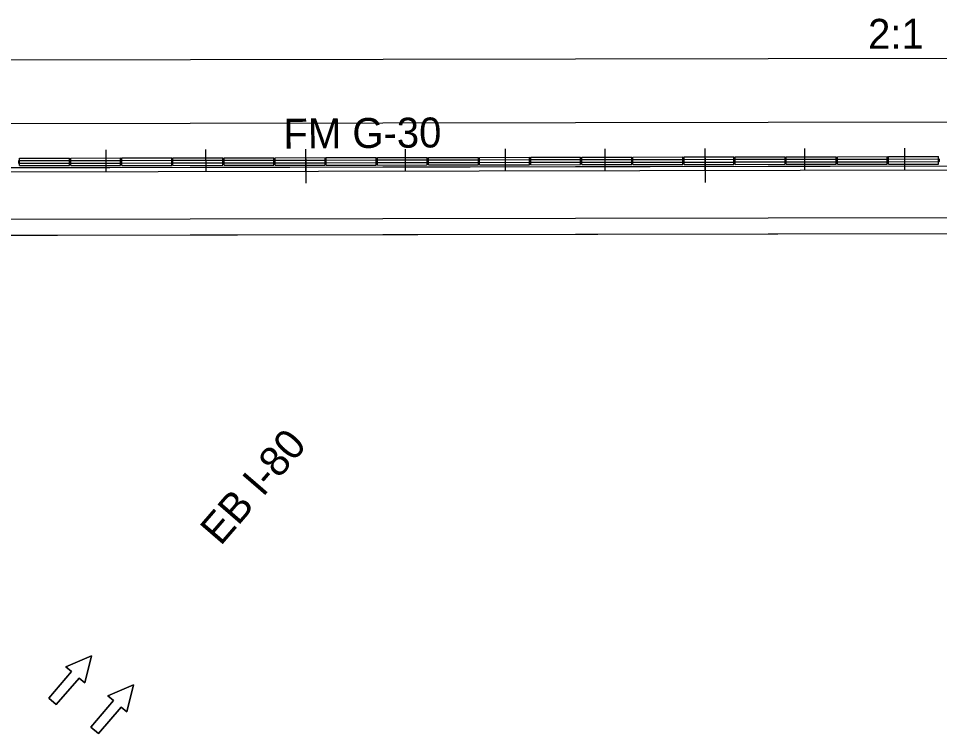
# Model space of a CAD drawing. Extents: x 16513048 to 16518780, y 7009856 to 7010869.
# Drawn here: x 16515768.8 to 16515999.5, y 7010216.8 to 7010396 of the extents above; entities that cross this region are included whole.
import ezdxf

# ---------------------------------------------------------------- set-up
doc = ezdxf.new("R2010")
doc.units = 0
for name, color, linetype in [('Dimensions', 7, 'Continuous'), ('dsnCellElements', 7, 'Continuous'), ('dsnNonPlotable', 7, 'Continuous'), ('EdgePaved', 7, 'Continuous'), ('Level 2', 7, 'Continuous'), ('Level 5', 7, 'Continuous'), ('Shape', 7, 'Continuous'), ('SheetBorder', 7, 'Continuous'), ('tdCoTitleBlock', 7, 'Continuous')]:
    doc.layers.add(name, color=color, linetype=linetype)

msp = doc.modelspace()

# ---------------------------------------------------------------- linework, layer by layer
at = {"layer": 'dsnCellElements'}
for p, q in [((16515922.71, 7010361.3), (16515935.21, 7010361.32)), ((16515935.22, 7010359.44), (16515935.21, 7010361.32)), ((16515935.52, 7010361.32), (16515948.02, 7010361.34)), ((16515935.52, 7010359.44), (16515935.52, 7010361.32)), ((16515948.02, 7010359.46), (16515948.02, 7010361.34)), ((16515948.32, 7010361.34), (16515960.82, 7010361.36)), ((16515948.32, 7010359.47), (16515948.32, 7010361.34)), ((16515960.82, 7010359.49), (16515960.82, 7010361.36)), ((16515961.12, 7010361.36), (16515973.62, 7010361.38)), ((16515961.12, 7010359.49), (16515961.12, 7010361.36)), ((16515973.62, 7010359.51), (16515973.62, 7010361.38)), ((16515973.92, 7010361.38), (16515986.42, 7010361.41)), ((16515973.93, 7010359.51), (16515973.92, 7010361.38)), ((16515986.43, 7010359.53), (16515986.42, 7010361.41)), ((16515986.73, 7010361.41), (16515999.23, 7010361.43)), ((16515986.73, 7010359.53), (16515986.73, 7010361.41)), ((16515999.23, 7010359.55), (16515999.23, 7010361.43)), ((16515769.09, 7010361.03), (16515781.59, 7010361.05)), ((16515769.09, 7010359.15), (16515769.09, 7010361.03)), ((16515769.09, 7010360.43), (16515781.59, 7010360.45)), ((16515769.09, 7010359.75), (16515781.59, 7010359.77)), ((16515769.09, 7010359.15), (16515781.59, 7010359.17)), ((16515781.59, 7010359.17), (16515781.59, 7010361.05)), ((16515781.89, 7010361.05), (16515794.39, 7010361.07)), ((16515781.89, 7010359.17), (16515781.89, 7010361.05)), ((16515781.89, 7010360.45), (16515794.39, 7010360.47)), ((16515781.89, 7010359.77), (16515794.39, 7010359.8)), ((16515781.89, 7010359.17), (16515794.39, 7010359.2)), ((16515794.39, 7010359.2), (16515794.39, 7010361.07)), ((16515794.69, 7010361.07), (16515807.19, 7010361.09)), ((16515794.7, 7010359.2), (16515794.69, 7010361.07)), ((16515794.69, 7010360.47), (16515807.19, 7010360.49)), ((16515794.7, 7010359.8), (16515807.2, 7010359.82)), ((16515794.7, 7010359.2), (16515807.2, 7010359.22)), ((16515807.2, 7010359.22), (16515807.19, 7010361.09)), ((16515807.5, 7010361.09), (16515820, 7010361.12)), ((16515807.5, 7010359.22), (16515807.5, 7010361.09)), ((16515807.5, 7010360.49), (16515820, 7010360.52)), ((16515807.5, 7010359.82), (16515820, 7010359.84)), ((16515807.5, 7010359.22), (16515820, 7010359.24)), ((16515820, 7010359.24), (16515820, 7010361.12)), ((16515820.3, 7010361.12), (16515832.8, 7010361.14)), ((16515820.3, 7010359.24), (16515820.3, 7010361.12)), ((16515820.3, 7010360.52), (16515832.8, 7010360.54)), ((16515820.3, 7010359.84), (16515832.8, 7010359.86)), ((16515820.3, 7010359.24), (16515832.8, 7010359.26)), ((16515832.8, 7010359.26), (16515832.8, 7010361.14)), ((16515833.1, 7010361.14), (16515845.6, 7010361.16)), ((16515833.1, 7010359.26), (16515833.1, 7010361.14)), ((16515833.1, 7010360.54), (16515845.6, 7010360.56)), ((16515833.1, 7010359.86), (16515845.6, 7010359.89)), ((16515833.1, 7010359.26), (16515845.6, 7010359.29)), ((16515845.6, 7010359.29), (16515845.6, 7010361.16)), ((16515845.9, 7010361.16), (16515858.4, 7010361.18)), ((16515845.91, 7010359.29), (16515845.9, 7010361.16)), ((16515845.9, 7010360.56), (16515858.4, 7010360.58)), ((16515845.9, 7010359.89), (16515858.4, 7010359.91)), ((16515845.91, 7010359.29), (16515858.41, 7010359.31)), ((16515858.41, 7010359.31), (16515858.4, 7010361.18)), ((16515858.7, 7010361.18), (16515871.2, 7010361.21)), ((16515858.71, 7010359.31), (16515858.7, 7010361.18)), ((16515858.71, 7010360.58), (16515871.21, 7010360.61)), ((16515858.71, 7010359.91), (16515871.21, 7010359.93)), ((16515858.71, 7010359.31), (16515871.21, 7010359.33)), ((16515871.21, 7010359.33), (16515871.2, 7010361.21)), ((16515871.51, 7010361.21), (16515884.01, 7010361.23)), ((16515871.51, 7010359.33), (16515871.51, 7010361.21)), ((16515871.51, 7010360.61), (16515884.01, 7010360.63)), ((16515871.51, 7010359.93), (16515884.01, 7010359.95)), ((16515871.51, 7010359.33), (16515884.01, 7010359.35)), ((16515884.01, 7010359.35), (16515884.01, 7010361.23)), ((16515884.31, 7010361.23), (16515896.81, 7010361.25)), ((16515884.31, 7010359.35), (16515884.31, 7010361.23)), ((16515884.31, 7010360.63), (16515896.81, 7010360.65)), ((16515884.31, 7010359.95), (16515896.81, 7010359.98)), ((16515884.31, 7010359.35), (16515896.81, 7010359.38)), ((16515896.81, 7010359.38), (16515896.81, 7010361.25)), ((16515897.11, 7010361.25), (16515909.61, 7010361.27)), ((16515897.11, 7010359.38), (16515897.11, 7010361.25)), ((16515897.11, 7010360.65), (16515909.61, 7010360.67)), ((16515897.11, 7010359.98), (16515909.61, 7010360)), ((16515897.11, 7010359.38), (16515909.61, 7010359.4)), ((16515909.61, 7010359.4), (16515909.61, 7010361.27)), ((16515909.91, 7010361.27), (16515922.41, 7010361.29)), ((16515909.92, 7010359.4), (16515909.91, 7010361.27)), ((16515909.91, 7010360.67), (16515922.41, 7010360.69)), ((16515909.91, 7010360), (16515922.41, 7010360.02)), ((16515909.92, 7010359.4), (16515922.42, 7010359.42)), ((16515922.42, 7010359.42), (16515922.41, 7010361.29)), ((16515922.72, 7010359.42), (16515922.71, 7010361.3)), ((16515922.72, 7010360.7), (16515935.22, 7010360.72)), ((16515922.72, 7010360.02), (16515935.22, 7010360.04)), ((16515922.72, 7010359.42), (16515935.22, 7010359.44)), ((16515935.52, 7010360.72), (16515948.02, 7010360.74)), ((16515935.52, 7010360.04), (16515948.02, 7010360.06)), ((16515935.52, 7010359.44), (16515948.02, 7010359.46)), ((16515948.32, 7010360.74), (16515960.82, 7010360.76)), ((16515948.32, 7010360.07), (16515960.82, 7010360.09)), ((16515948.32, 7010359.47), (16515960.82, 7010359.49)), ((16515961.12, 7010360.76), (16515973.62, 7010360.78)), ((16515961.12, 7010360.09), (16515973.62, 7010360.11)), ((16515961.12, 7010359.49), (16515973.62, 7010359.51)), ((16515973.92, 7010360.78), (16515986.42, 7010360.81)), ((16515973.93, 7010360.11), (16515986.43, 7010360.13)), ((16515973.93, 7010359.51), (16515986.43, 7010359.53)), ((16515986.73, 7010360.81), (16515999.23, 7010360.83)), ((16515986.73, 7010360.13), (16515999.23, 7010360.15)), ((16515986.73, 7010359.53), (16515999.23, 7010359.55))]:
    msp.add_line(p, q, dxfattribs=at)
at = {"layer": 'dsnNonPlotable'}
msp.add_line((16513050.27, 7010352.91), (16516699.62, 7010359.27), dxfattribs=at)
for points in [[(16513050.22, 7010380.91), (16516699.59, 7010387.27), (16518770.65, 7010388.94)], [(16518770.66, 7010372.94), (16516699.61, 7010371.27), (16513050.25, 7010364.91)], [(16518770.68, 7010348.94), (16516699.64, 7010347.27), (16513050.29, 7010340.91)], [(16518770.69, 7010344.94), (16516699.64, 7010343.27), (16513050.3, 7010336.91)]]:
    msp.add_lwpolyline(points, dxfattribs=at)
at = {"layer": 'EdgePaved'}
for centre in [(16515768.94, 7010360.09), (16515768.94, 7010360.09), (16515781.74, 7010360.11), (16515781.74, 7010360.11), (16515794.54, 7010360.13), (16515794.54, 7010360.13), (16515807.35, 7010360.16), (16515807.35, 7010360.16), (16515820.15, 7010360.18), (16515820.15, 7010360.18), (16515832.95, 7010360.2), (16515832.95, 7010360.2), (16515845.75, 7010360.22), (16515845.75, 7010360.22), (16515858.55, 7010360.25), (16515858.55, 7010360.25), (16515871.36, 7010360.27), (16515871.36, 7010360.27), (16515884.16, 7010360.29), (16515884.16, 7010360.29), (16515896.96, 7010360.31), (16515896.96, 7010360.31), (16515909.76, 7010360.34), (16515909.76, 7010360.34), (16515922.57, 7010360.36), (16515922.57, 7010360.36), (16515935.37, 7010360.38), (16515935.37, 7010360.38), (16515948.17, 7010360.4), (16515948.17, 7010360.4), (16515960.97, 7010360.42), (16515960.97, 7010360.42), (16515973.77, 7010360.45), (16515973.77, 7010360.45), (16515986.58, 7010360.47), (16515986.58, 7010360.47), (16515999.38, 7010360.49), (16515999.38, 7010360.49)]:
    msp.add_circle(centre, 0.0521, dxfattribs=at)
for centre, start, end in [((16515768.79, 7010360.09), 270.0999, 90.0999), ((16515769.09, 7010360.09), 90.0999, 270.0999), ((16515781.59, 7010360.11), 270.0999, 90.0999), ((16515781.89, 7010360.11), 90.0999, 270.0999), ((16515794.39, 7010360.13), 270.0999, 90.0999), ((16515794.69, 7010360.13), 90.0999, 270.0999), ((16515807.2, 7010360.16), 270.0999, 90.0999), ((16515807.5, 7010360.16), 90.0999, 270.0999), ((16515820, 7010360.18), 270.0999, 90.0999), ((16515820.3, 7010360.18), 90.0999, 270.0999), ((16515832.8, 7010360.2), 270.0999, 90.0999), ((16515833.1, 7010360.2), 90.0999, 270.0999), ((16515845.6, 7010360.22), 270.0999, 90.0999), ((16515845.9, 7010360.22), 90.0999, 270.0999), ((16515858.4, 7010360.25), 270.0999, 90.0999), ((16515858.71, 7010360.25), 90.0999, 270.0999), ((16515871.21, 7010360.27), 270.0999, 90.0999), ((16515871.51, 7010360.27), 90.0999, 270.0999), ((16515884.01, 7010360.29), 270.0999, 90.0999), ((16515884.31, 7010360.29), 90.0999, 270.0999), ((16515896.81, 7010360.31), 270.0999, 90.0999), ((16515897.11, 7010360.31), 90.0999, 270.0999), ((16515909.61, 7010360.34), 270.0999, 90.0999), ((16515909.91, 7010360.34), 90.0999, 270.0999), ((16515922.41, 7010360.36), 270.0999, 90.0999), ((16515922.72, 7010360.36), 90.0999, 270.0999), ((16515935.22, 7010360.38), 270.0999, 90.0999), ((16515935.52, 7010360.38), 90.0999, 270.0999), ((16515948.02, 7010360.4), 270.0999, 90.0999), ((16515948.32, 7010360.4), 90.0999, 270.0999), ((16515960.82, 7010360.42), 270.0999, 90.0999), ((16515961.12, 7010360.42), 90.0999, 270.0999), ((16515973.62, 7010360.45), 270.0999, 90.0999), ((16515973.92, 7010360.45), 90.0999, 270.0999), ((16515986.42, 7010360.47), 270.0999, 90.0999), ((16515986.73, 7010360.47), 90.0999, 270.0999), ((16515999.23, 7010360.49), 270.0999, 90.0999), ((16515999.53, 7010360.49), 90.0999, 270.0999)]:
    msp.add_arc(centre, 0.281, start, end, dxfattribs=at)
at = {"layer": 'Level 2'}
for points in [[(16515778.29, 7010224.09), (16515776.39, 7010225.72), (16515782.08, 7010232.36), (16515780.66, 7010233.58), (16515787.1, 7010236.29), (16515785.4, 7010229.51), (16515783.98, 7010230.73)], [(16515788.84, 7010216.83), (16515786.94, 7010218.46), (16515792.64, 7010225.1), (16515791.21, 7010226.32), (16515797.65, 7010229.04), (16515795.96, 7010222.26), (16515794.54, 7010223.48)]]:
    msp.add_lwpolyline(points, close=True, dxfattribs=at)
at = {"layer": 'Level 5'}
for points in [[(16515783.98, 7010230.73), (16515785.4, 7010229.51), (16515787.1, 7010236.29), (16515780.66, 7010233.58), (16515782.08, 7010232.36), (16515776.39, 7010225.72), (16515778.29, 7010224.09), (16515783.98, 7010230.73)], [(16515794.54, 7010223.48), (16515795.96, 7010222.26), (16515797.65, 7010229.04), (16515791.21, 7010226.32), (16515792.64, 7010225.1), (16515786.94, 7010218.46), (16515788.84, 7010216.83), (16515794.54, 7010223.48)]]:
    msp.add_lwpolyline(points, dxfattribs=at)
at = {"layer": 'Shape'}
msp.add_line((16516114.45, 7010359.25), (16515602.67, 7010358.36), dxfattribs=at)
msp.add_lwpolyline([(16516017.16, 7010359.09), (16516004.05, 7010342.06), (16515688.36, 7010341.51), (16515701.47, 7010358.53), (16516017.16, 7010359.09)], close=True, dxfattribs=at)
at = {"layer": 'SheetBorder'}
for p, q in [((16515790.79, 7010357.69), (16515790.78, 7010363.15)), ((16515815.79, 7010357.73), (16515815.78, 7010363.19)), ((16515865.79, 7010357.82), (16515865.78, 7010363.28)), ((16515890.79, 7010357.86), (16515890.78, 7010363.32)), ((16515915.79, 7010357.91), (16515915.78, 7010363.37)), ((16515965.79, 7010358), (16515965.78, 7010363.46)), ((16515990.79, 7010358.04), (16515990.78, 7010363.5)), ((16515840.78, 7010360.84), (16515840.8, 7010354.72)), ((16515940.78, 7010361.01), (16515940.8, 7010354.89))]:
    msp.add_line(p, q, dxfattribs=at)
at = {"layer": 'tdCoTitleBlock'}
for p, q in [((16515840.79, 7010357.78), (16515840.78, 7010363.24)), ((16515940.79, 7010357.95), (16515940.78, 7010363.41))]:
    msp.add_line(p, q, dxfattribs=at)

# ---------------------------------------------------------------- texts
at = {"layer": 'Dimensions'}
for s, rotation, p in [('FM G-30', 0.4439, (16515835.2, 7010363.42)), ('EB I-80', 49.1804, (16515819.43, 7010263.68))]:
    msp.add_text(s, height=7.5, rotation=rotation, dxfattribs=at).set_placement(p)
at = {"layer": 'dsnNonPlotable'}
msp.add_text('2:1', height=7.5, rotation=0.0999, dxfattribs=at).set_placement((16515981.62, 7010388.42))

doc.saveas('drawing.dxf')
